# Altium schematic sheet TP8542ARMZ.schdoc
size 127 x 101 mm
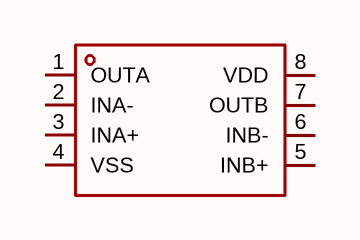
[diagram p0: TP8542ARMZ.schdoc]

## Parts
U?  tp8542armz  [MSOP-8_L3.0-W3.0-P0.65-LS4.9-BL]  (value not drawn)

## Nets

Not connected (* = marked no-connect by the designer): U? 1(OUTA) 2(INA-) 3(INA+) 4(VSS) 5(INB+) 6(INB-) 7(OUTB) 8(VDD)

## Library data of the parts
U? = tp8542armz: 放大器数:2;轨到轨:轨到轨输入,轨到轨输出;增益带宽积(GBW):1MHz;输入失调电压(Vos):5mV;压摆率(SR):600V/ms;输入偏置电流(Ib):10pA;; Manufacturer: TECH PUBLIC(台舟); AddInBom: yes; ModelId: bedc0aeebe0a475e87aaac88bd02a14b; ModelName: MSOP-8_L3.0-W3.0-H1.1-LS4.9-P0.65; ModelTransform: 118.11,192.913,0,0,0,0,0,0,0; Number of Channels: 2; Maximum Power Supply Range (Vdd-Vss): 7V; Gain Bandwidth Product: 1MHz; Vos - Input Offset Voltage: 5mV; Input Offset Voltage Drift(Vos TC): 2uV/℃; Ib - Input Bias Current: 10pA; Input Voltage Noise Density: 20nV/√Hz@10kHz; Common Mode Rejection Ratio(CMRR): 80dB; Quiescent Current: 80uA; Output Current: 20mA; Single supply: 2.5V~5.5V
